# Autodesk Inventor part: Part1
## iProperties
Author: Elise Moss
Created: 2001-09
Part Number: Part1
Document SubType Name: Modeling
Designer: Elise Moss
Control State: 0
Master: False
Checked Out: False
PropertySet Name: Design Tracking Control
Shininess: 64.0
Angle Display Precision: 2
Document Length Units: 11272
Document Angle Units: 11286
Document Time Units: 11279
Document Mass Units: 11290
Document Length Units Precision: 3
Document Angle Units Precision: 2
Compacted: True
PropertySet Name: _Private Model Information
Density: 0.0
Volumn: 0.0
Area: 0.0
PropertySet Name: Model Information
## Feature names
1. Extrusion1
2. Chamfer1
